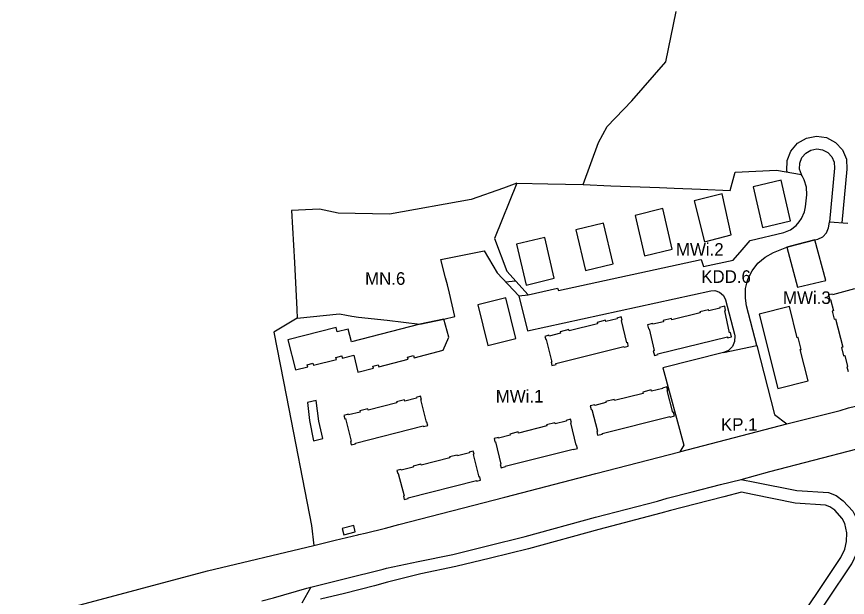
# Model space of a CAD drawing. Extents: x 7414808 to 7417449, y 5544732 to 5546764.
# Drawn here: x 7415189.8 to 7415519.6, y 5545829.9 to 5546060.4 of the extents above; entities that cross this region are included whole.
import ezdxf

# ---------------------------------------------------------------- set-up
doc = ezdxf.new("R2010")
doc.units = 0
for name, color, linetype in [('LIN_Linie Rozgraniczajace', 7, 'Continuous'), ('LIN_nieprzekraczale linie zabudowy', 7, 'Continuous'), ('LIN_obowiązujące linie zabudowy', 7, 'Continuous'), ('TXT_Oznaczenia Przeznaczenia', 7, 'Continuous')]:
    doc.layers.add(name, color=color, linetype=linetype)

msp = doc.modelspace()

# ---------------------------------------------------------------- linework, layer by layer
at = {"layer": 'LIN_Linie Rozgraniczajace'}
for points in [[(7415414.67, 5545993.75), (7415420.78, 5546010.4), (7415424.18, 5546016.76), (7415434.02, 5546027.02), (7415447.45, 5546042.45), (7415451.61, 5546062.42)], [(7415501.32, 5545997.74), (7415500.62, 5545999.9), (7415500.68, 5546002.26), (7415501.52, 5546004.46), (7415503.04, 5546006.26), (7415505.08, 5546007.46), (7415507.39, 5546007.91), (7415509.72, 5546007.56), (7415511.81, 5546006.46), (7415513.41, 5546004.73), (7415514.35, 5546002.57), (7415514.52, 5546000.22), (7415512.41, 5545978.97)], [(7415414.67, 5545993.75), (7415425.72, 5545993.3), (7415444.96, 5545992.55), (7415450.78, 5545992.32), (7415461.31, 5545991.9), (7415473.04, 5545991.44), (7415475.03, 5545998.64), (7415491.38, 5545999.48), (7415501.32, 5545997.74)], [(7415392.82, 5545949.91), (7415404.5, 5545952.61), (7415404.93, 5545951.67), (7415461.57, 5545964.04), (7415462.5, 5545961.17), (7415474.25, 5545963.73), (7415477.87, 5545967.88), (7415481.02, 5545971.49), (7415494.37, 5545974.67), (7415497, 5545975.71), (7415499.23, 5545977.43), (7415500.4, 5545978.89), (7415501.34, 5545980.32), (7415502.54, 5545982.87), (7415502.94, 5545984.84), (7415503.42, 5545989.6), (7415503.32, 5545992.69), (7415502.44, 5545995.65), (7415501.63, 5545997.18), (7415501.35, 5545997.66), (7415501.32, 5545997.74)], [(7415388.36, 5545994.36), (7415383.06, 5545992.27), (7415370.25, 5545987.85), (7415337.85, 5545981.98), (7415317.42, 5545982.38), (7415310.03, 5545983.93), (7415298.93, 5545983.5), (7415300.11, 5545962.76), (7415301.02, 5545944.1), (7415301.2, 5545940.68)], [(7415388.36, 5545994.36), (7415379.48, 5545972.32), (7415384.32, 5545959.38), (7415392.82, 5545949.91)], [(7415388.36, 5545994.36), (7415400.65, 5545994.07), (7415414.67, 5545993.75)], [(7415483.59, 5545929.91), (7415479.58, 5545945.62), (7415479.08, 5545948.65), (7415479.18, 5545952.44), (7415480.07, 5545956.12), (7415481.71, 5545959.54), (7415484.04, 5545962.53), (7415486.93, 5545964.98), (7415490.28, 5545966.76), (7415495.53, 5545968.88), (7415499.56, 5545969.91), (7415506.68, 5545971.78), (7415507.8, 5545972.07), (7415509.77, 5545973), (7415511.28, 5545974.58), (7415512.13, 5545976.58), (7415512.24, 5545977.28), (7415512.41, 5545978.97)], [(7415512.41, 5545978.97), (7415519.74, 5545978.47)], [(7415301.2, 5545940.68), (7415317.92, 5545942.41), (7415320.74, 5545941.85), (7415322.83, 5545941.44), (7415325.51, 5545941.11), (7415336.83, 5545939.86), (7415349.79, 5545938.28), (7415359.36, 5545940.36), (7415363.8, 5545941.32), (7415361.58, 5545950.61), (7415360.78, 5545953.96), (7415360.04, 5545956.7), (7415358.19, 5545963.99), (7415375.37, 5545967.49), (7415380.6, 5545958.74), (7415389.18, 5545949.59)], [(7415389.18, 5545949.59), (7415392.57, 5545935.66), (7415465.31, 5545951.55), (7415466.94, 5545951.63), (7415468.83, 5545951.01), (7415470.34, 5545949.71), (7415471.21, 5545947.92), (7415474.75, 5545934.35), (7415474.89, 5545933.65), (7415474.79, 5545931.47), (7415473.92, 5545929.47), (7415472.38, 5545927.92), (7415470.4, 5545927.01)], [(7415389.18, 5545949.59), (7415392.82, 5545949.91)], [(7415301.2, 5545940.68), (7415291.92, 5545935.16), (7415296.9, 5545909.47), (7415306.81, 5545858.33), (7415307.77, 5545850.49)], [(7415470.4, 5545927.01), (7415483.59, 5545929.91)], [(7415483.59, 5545929.91), (7415490.59, 5545902.51), (7415495.49, 5545898.77)], [(7415470.4, 5545927.01), (7415446.27, 5545921.01), (7415454.68, 5545890.26), (7415453.04, 5545887.66)], [(7415495.49, 5545898.77), (7415516.69, 5545904.1), (7415519.97, 5545905.14), (7415537.93, 5545909.37)], [(7415453.04, 5545887.66), (7415453.48, 5545887.77), (7415495.49, 5545898.77)], [(7415307.77, 5545850.49), (7415316.27, 5545852.51), (7415325.18, 5545854.64), (7415325.66, 5545854.76), (7415328.18, 5545855.38), (7415336.21, 5545857.39), (7415341.46, 5545858.75), (7415383.59, 5545869.67), (7415419.76, 5545879.04), (7415453.04, 5545887.66)], [(7415477.36, 5545876.7), (7415488.81, 5545879.82), (7415523.4, 5545888.77)], [(7415306.62, 5545833.93), (7415319.82, 5545837.23), (7415335.33, 5545841.12), (7415336.6, 5545841.39), (7415349.24, 5545844.04), (7415362.97, 5545846.94), (7415376.74, 5545850.35), (7415391.66, 5545854), (7415419.61, 5545861.66), (7415444.16, 5545868.09), (7415448.07, 5545869.23), (7415457.94, 5545871.75), (7415469.27, 5545874.63), (7415477.36, 5545876.7)], [(7415477.36, 5545876.7), (7415482.86, 5545875.66), (7415499.48, 5545872.28), (7415512.05, 5545871.46), (7415515.09, 5545870.26), (7415517.91, 5545868.19), (7415521.74, 5545864.02), (7415523.26, 5545860.87), (7415523.85, 5545858.38), (7415524.45, 5545855.9)], [(7415480.78, 5545727.12), (7415483.24, 5545729.05), (7415482.96, 5545743.71), (7415483.01, 5545750.02), (7415483.36, 5545755.98), (7415483.69, 5545759.38), (7415484.11, 5545762.65), (7415484.85, 5545767.3), (7415485.36, 5545769.95), (7415486, 5545772.89), (7415486.78, 5545776.08), (7415487.58, 5545779), (7415488.59, 5545782.35), (7415489.61, 5545785.4), (7415494.82, 5545800.38), (7415495.83, 5545803.08), (7415496.97, 5545805.76), (7415498.25, 5545808.39), (7415499.87, 5545811.19), (7415501.45, 5545813.54), (7415521.39, 5545843.2), (7415523.29, 5545847.45), (7415524.15, 5545851.33), (7415524.45, 5545855.9)], [(7414998.29, 5545778.83), (7415029.23, 5545783.64), (7415077.77, 5545791.68), (7415111.05, 5545799.42), (7415162.88, 5545813.44), (7415210.97, 5545825.8), (7415265.57, 5545840.42), (7415307.77, 5545850.49)], [(7415287.07, 5545828.44), (7415291.72, 5545829.65), (7415305.05, 5545833.54), (7415306.62, 5545833.93)], [(7415306.62, 5545833.93), (7415303, 5545827.57)]]:
    msp.add_lwpolyline(points, dxfattribs=at)
at = {"layer": 'LIN_nieprzekraczale linie zabudowy'}
for points in [[(7415495.75, 5545998.71), (7415495.6, 5545999.17), (7415495.7, 5546003.24), (7415497.15, 5546007.04), (7415499.78, 5546010.14), (7415503.28, 5546012.2), (7415507.28, 5546012.98), (7415511.3, 5546012.38), (7415514.9, 5546010.49), (7415517.66, 5546007.5), (7415519.28, 5546003.77), (7415519.32, 5545999.81), (7415517.39, 5545978.55)], [(7415383.96, 5545955.15), (7415387.68, 5545955.48)], [(7415495.63, 5545813.84), (7415517, 5545845.63), (7415518.51, 5545849.03), (7415519.19, 5545852.04), (7415519.41, 5545855.47), (7415518.52, 5545859.18), (7415517.56, 5545861.19), (7415514.56, 5545864.45), (7415512.66, 5545865.85), (7415510.95, 5545866.52), (7415498.82, 5545867.31), (7415481.9, 5545870.75), (7415477.52, 5545871.58), (7415470.51, 5545869.79), (7415459.17, 5545866.9), (7415449.39, 5545864.41), (7415445.49, 5545863.27), (7415420.9, 5545856.83), (7415392.92, 5545849.16), (7415377.94, 5545845.49), (7415364.09, 5545842.07), (7415350.27, 5545839.15), (7415336.97, 5545835.93), (7415331.88, 5545834.5), (7415319.99, 5545831.43), (7415310.45, 5545829.1)]]:
    msp.add_lwpolyline(points, dxfattribs=at)
at = {"layer": 'LIN_obowiązujące linie zabudowy'}
for points in [[(7415485.92, 5545976.68), (7415497.05, 5545979.33), (7415493.33, 5545995.53), (7415482.14, 5545992.88)], [(7415462.79, 5545971.01), (7415473.5, 5545973.76), (7415469.89, 5545990.05), (7415458.73, 5545987.26)], [(7415439.02, 5545965.41), (7415450.01, 5545968.11), (7415446.32, 5545984.2), (7415435.37, 5545981.44)], [(7415415.58, 5545959.64), (7415426.59, 5545962.3), (7415422.76, 5545978.43), (7415411.83, 5545975.74)], [(7415392.03, 5545953.77), (7415403.17, 5545956.54), (7415399.41, 5545972.79), (7415388.2, 5545970.11)], [(7415499.81, 5545952.96), (7415511, 5545955.72), (7415506.68, 5545971.78), (7415499.56, 5545969.91), (7415495.53, 5545968.88)], [(7415376.8, 5545929.86), (7415387.95, 5545932.63), (7415383.98, 5545948.78), (7415372.81, 5545945.97)], [(7415461.11, 5545942.76), (7415449.92, 5545940.09), (7415449.81, 5545940.53), (7415449.81, 5545940.53), (7415446.41, 5545939.77), (7415446.52, 5545939.26), (7415442.3, 5545938.31), (7415442.22, 5545938.59), (7415440.28, 5545938.07), (7415440.6, 5545936.45), (7415440.92, 5545936.51), (7415442.83, 5545927.81), (7415442.51, 5545927.73), (7415442.96, 5545925.9), (7415444.43, 5545926.28), (7415444.36, 5545926.55), (7415471.94, 5545933.24), (7415472.02, 5545932.9), (7415473.54, 5545933.25), (7415473.12, 5545935.01), (7415472.81, 5545934.93), (7415470.93, 5545943.63), (7415471.25, 5545943.69), (7415470.92, 5545945.44), (7415468.84, 5545944.94), (7415468.92, 5545944.61), (7415464.6, 5545943.58), (7415464.48, 5545944.06), (7415464.48, 5545944.06), (7415461, 5545943.21)], [(7415500.89, 5545928.23), (7415501.29, 5545928.33), (7415500.08, 5545933.05), (7415499.7, 5545932.95), (7415496.55, 5545945.31), (7415484.53, 5545942.3), (7415492, 5545912.73), (7415504.06, 5545915.78)], [(7415300.49, 5545920.17), (7415305.4, 5545921.43), (7415305.17, 5545922.24), (7415307.41, 5545922.81), (7415307.62, 5545921.99), (7415316.71, 5545924.27), (7415316.49, 5545925.12), (7415318.86, 5545925.73), (7415319.05, 5545924.88), (7415323.6, 5545926.02), (7415325.29, 5545919.3), (7415331.43, 5545920.85), (7415331.21, 5545921.68), (7415333.37, 5545922.24), (7415333.59, 5545921.39), (7415345.22, 5545924.39), (7415345, 5545925.23), (7415347.34, 5545925.83), (7415347.55, 5545924.97), (7415359.08, 5545928.01), (7415361.32, 5545933.13), (7415359.36, 5545940.36), (7415349.79, 5545938.28), (7415322.69, 5545931.33), (7415321.37, 5545936.33), (7415317.08, 5545935.26), (7415316.69, 5545936.95), (7415297.43, 5545932.04)], [(7415402.31, 5545921.91), (7415403.97, 5545922.32), (7415403.97, 5545922.32), (7415403.97, 5545922.32), (7415403.88, 5545922.66), (7415430.85, 5545929.45), (7415430.93, 5545929.17), (7415432.61, 5545929.62), (7415432.36, 5545930.93), (7415432.04, 5545930.87), (7415429.84, 5545939.81), (7415430.19, 5545939.92), (7415429.79, 5545941.2), (7415428.09, 5545940.75), (7415428.17, 5545940.42), (7415423.67, 5545939.37), (7415423.53, 5545939.89), (7415420.21, 5545939), (7415420.35, 5545938.5), (7415409.18, 5545935.65), (7415409.02, 5545936.19), (7415405.61, 5545935.34), (7415405.74, 5545934.81), (7415401.21, 5545933.6), (7415401.11, 5545933.94), (7415399.46, 5545933.49), (7415399.8, 5545932.2), (7415400.05, 5545932.27), (7415402.22, 5545923.3), (7415401.96, 5545923.23)], [(7415438.56, 5545910.85), (7415427.1, 5545908.01), (7415427.01, 5545908.46), (7415423.63, 5545907.65), (7415423.75, 5545907.16), (7415419.33, 5545906.06), (7415419.29, 5545906.28), (7415417.53, 5545905.89), (7415417.88, 5545904.44), (7415418.1, 5545904.49), (7415420.35, 5545895.78), (7415420.07, 5545895.71), (7415420.44, 5545894.2), (7415422.31, 5545894.69), (7415422.24, 5545894.97), (7415449.14, 5545901.66), (7415449.2, 5545901.43), (7415450.88, 5545901.88), (7415450.51, 5545903.33), (7415450.3, 5545903.27), (7415448.07, 5545911.96), (7415448.28, 5545912.02), (7415447.9, 5545913.42), (7415446.21, 5545912.98), (7415446.25, 5545912.8), (7415441.82, 5545911.68), (7415441.71, 5545912.23), (7415438.42, 5545911.35)], [(7415307.62, 5545891.97), (7415311.29, 5545892.93), (7415309.75, 5545899.87), (7415308.63, 5545908.04), (7415305.31, 5545907.17), (7415306.03, 5545900.07)], [(7415322.61, 5545890.44), (7415324.32, 5545890.87), (7415324.26, 5545891.13), (7415351.22, 5545897.92), (7415351.27, 5545897.71), (7415352.99, 5545898.12), (7415352.68, 5545899.43), (7415352.52, 5545899.4), (7415350.25, 5545908.35), (7415350.45, 5545908.4), (7415350.14, 5545909.68), (7415348.4, 5545909.22), (7415348.46, 5545908.98), (7415343.91, 5545907.81), (7415343.78, 5545908.29), (7415340.59, 5545907.52), (7415340.71, 5545907.04), (7415329.29, 5545904.19), (7415329.16, 5545904.72), (7415326.02, 5545903.88), (7415326.14, 5545903.44), (7415321.53, 5545902.27), (7415321.43, 5545902.57), (7415319.71, 5545902.1), (7415320.08, 5545900.75), (7415320.35, 5545900.82), (7415322.54, 5545891.82), (7415322.28, 5545891.76)], [(7415382.08, 5545881.33), (7415383.82, 5545881.76), (7415383.77, 5545881.95), (7415410.73, 5545888.75), (7415410.77, 5545888.59), (7415412.42, 5545888.99), (7415412.1, 5545890.27), (7415411.92, 5545890.22), (7415409.77, 5545899.19), (7415409.99, 5545899.25), (7415409.65, 5545900.56), (7415407.93, 5545900.08), (7415407.99, 5545899.86), (7415403.52, 5545898.73), (7415403.4, 5545899.2), (7415400.09, 5545898.39), (7415400.21, 5545897.9), (7415388.97, 5545895.09), (7415388.84, 5545895.58), (7415385.56, 5545894.71), (7415385.69, 5545894.2), (7415381.14, 5545893.08), (7415381.09, 5545893.3), (7415379.35, 5545892.92), (7415379.67, 5545891.57), (7415379.83, 5545891.61), (7415382.05, 5545882.72), (7415381.79, 5545882.65)], [(7415340.77, 5545880.27), (7415341.05, 5545878.98), (7415341.31, 5545879.04), (7415343.58, 5545870.15), (7415343.32, 5545870.08), (7415343.67, 5545868.74), (7415345.26, 5545869.13), (7415345.2, 5545869.37), (7415372.32, 5545876.21), (7415372.37, 5545875.99), (7415373.99, 5545876.36), (7415373.69, 5545877.65), (7415373.4, 5545877.58), (7415371.15, 5545886.59), (7415371.15, 5545886.59), (7415371.38, 5545886.65), (7415371.05, 5545887.89), (7415369.49, 5545887.46), (7415369.55, 5545887.22), (7415364.81, 5545886.01), (7415364.71, 5545886.38), (7415361.66, 5545885.61), (7415361.76, 5545885.24), (7415350.31, 5545882.36), (7415350.21, 5545882.73), (7415347.16, 5545881.97), (7415347.26, 5545881.59), (7415342.4, 5545880.42), (7415342.35, 5545880.63)], [(7415319.63, 5545854.71), (7415324.22, 5545855.87), (7415323.6, 5545858.4), (7415319.02, 5545857.24)]]:
    msp.add_lwpolyline(points, close=True, dxfattribs=at)
msp.add_lwpolyline([(7415522.34, 5545952.33), (7415513.63, 5545950.03), (7415513.57, 5545950.28), (7415512.14, 5545949.95), (7415512.67, 5545948.05), (7415512.91, 5545948.12), (7415514.06, 5545943.64), (7415513.54, 5545943.51), (7415514.39, 5545940.26), (7415514.84, 5545940.38), (7415517.71, 5545929.19), (7415517.21, 5545929.07), (7415518.07, 5545925.76), (7415518.57, 5545925.89), (7415519.68, 5545921.45), (7415519.39, 5545921.38), (7415519.87, 5545919.48)], dxfattribs=at)

# ---------------------------------------------------------------- texts
at = {"layer": 'TXT_Oznaczenia Przeznaczenia'}
for s, p in [('MWi.2', (7415451.52, 5545965.48)), ('KDD.6', (7415461.56, 5545954.71)), ('MN.6', (7415328.11, 5545953.95)), ('MWi.3', (7415494.02, 5545946.35)), ('MWi.1', (7415379.99, 5545907.22)), ('KP.1', (7415469.39, 5545896))]:
    msp.add_text(s, height=5, dxfattribs=at).set_placement(p)

doc.saveas('drawing.dxf')
